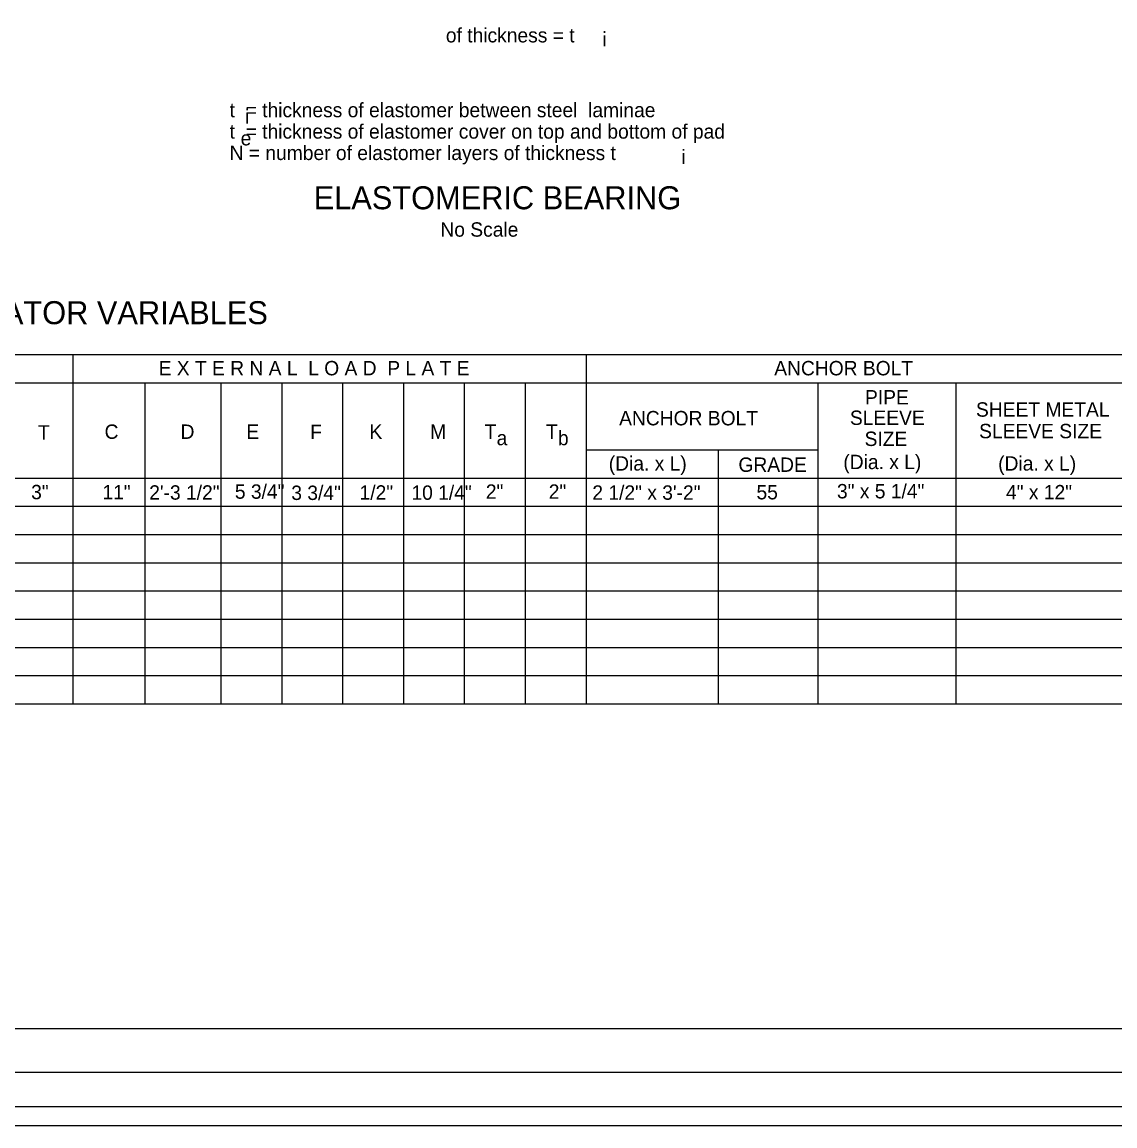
# Model space of a CAD drawing. Extents: x -194 to 226, y 505 to 725.
# Drawn here: x -47.4 to 47.6, y 505.4 to 601.4 of the extents above; entities that cross this region are included whole.
import ezdxf

# ---------------------------------------------------------------- set-up
doc = ezdxf.new("R2010")
doc.units = 0
for name, color, linetype in [('border', 7, 'Continuous'), ('Border 2660-Hwy18 - Level 62', 7, 'Continuous'), ('Border 2660-Hwy18 - Level 63', 7, 'Continuous'), ('Level 40', 7, 'Continuous'), ('Level 41', 7, 'Continuous'), ('Level 62 PDF', 7, 'Continuous'), ('Text', 7, 'Continuous')]:
    doc.layers.add(name, color=color, linetype=linetype)

msp = doc.modelspace()

# ---------------------------------------------------------------- linework, layer by layer
at = {"layer": 'border'}
msp.add_line((143.779, 513.86), (-176.332, 513.86), dxfattribs=at)
at = {"layer": 'Border 2660-Hwy18 - Level 62'}
msp.add_lwpolyline([(-192.533, 725.169), (148.651, 725.169), (148.651, 507.073), (-192.533, 507.073)], close=True, dxfattribs=at)
at = {"layer": 'Border 2660-Hwy18 - Level 63'}
msp.add_lwpolyline([(-193.644, 723.74), (146.351, 723.74), (146.351, 510.044), (-193.644, 510.044)], close=True, dxfattribs=at)
at = {"layer": 'Level 40'}
for p, q in [((-36.746, 570.011), (-36.746, 542.092)), ((-30.142, 570.011), (-30.142, 542.092)), ((-24.854, 570.011), (-24.854, 542.092)), ((-19.563, 570.011), (-19.563, 542.092)), ((-14.271, 570.011), (-14.271, 542.092)), ((-8.979, 570.011), (-8.979, 542.092)), ((-3.688, 570.011), (-3.688, 542.092)), ((0.214, 570.011), (5.33, 570.011)), ((21.757, 570.011), (21.757, 542.092)), ((33.757, 570.011), (33.757, 542.092)), ((1.604, 564.172), (21.757, 564.172)), ((13.084, 564.172), (13.084, 542.092)), ((-173.559, 561.719), (58.082, 561.719)), ((-42.997, 562.218), (-42.997, 558.728)), ((-36.746, 562.218), (-36.746, 558.728)), ((-30.142, 562.218), (-30.142, 558.728)), ((-24.854, 562.218), (-24.854, 558.728)), ((1.604, 562.218), (1.604, 558.728)), ((21.757, 562.218), (21.757, 558.728)), ((33.757, 562.218), (33.757, 558.728)), ((-173.559, 559.266), (58.082, 559.266)), ((-173.559, 556.812), (58.082, 556.812)), ((-173.559, 556.812), (58.082, 556.812)), ((-173.559, 554.359), (58.082, 554.359)), ((-173.559, 554.359), (58.082, 554.359)), ((-173.559, 551.906), (58.082, 551.906)), ((-173.559, 551.905), (58.082, 551.905)), ((-173.559, 549.452), (58.082, 549.452)), ((-173.559, 546.999), (58.082, 546.999)), ((-173.559, 544.545), (58.082, 544.545))]:
    msp.add_line(p, q, dxfattribs=at)
at = {"layer": 'Level 41'}
for p, q in [((-92.484, 572.464), (58.082, 572.464)), ((-42.997, 572.464), (-42.997, 542.092)), ((1.604, 572.464), (1.604, 542.092)), ((-173.559, 570.011), (58.082, 570.011)), ((-173.559, 542.092), (58.082, 542.092))]:
    msp.add_line(p, q, dxfattribs=at)
at = {"layer": 'Level 62 PDF'}
msp.add_lwpolyline([(-190.033, 723.503), (151.151, 723.503), (151.151, 505.407), (-190.033, 505.407)], close=True, dxfattribs=at)

# ---------------------------------------------------------------- texts
at = {"layer": 'Level 40'}
for s, p in [('of thickness = t', (-10.582, 599.588)), ('t  = thickness of elastomer between steel  laminae', (-29.384, 593.086)), ('t  = thickness of elastomer cover on top and bottom of pad', (-29.384, 591.224)), ('e', (-28.422, 590.636)), ('N = number of elastomer layers of thickness t', (-29.384, 589.363)), ('No Scale', (-11.059, 582.702)), ('E X T E R N A L  L O A D  P L A T E ', (-35.554, 570.65)), ('ANCHOR BOLT', (17.968, 570.65)), ('PIPE', (25.857, 568.117)), ('SHEET METAL', (35.506, 567.055)), ('ANCHOR BOLT', (4.482, 566.303)), ('SLEEVE', (24.546, 566.339)), ('T', (-46.037, 565.067)), ('C', (-40.252, 565.128)), ('D', (-33.644, 565.128)), ('E', (-27.931, 565.128)), ('F', (-22.376, 565.102)), ('K', (-17.224, 565.128)), ('M', (-11.952, 565.128)), ('T ', (-7.213, 565.128)), ('T ', (-1.884, 565.128)), ('SLEEVE SIZE', (35.779, 565.182)), ('a ', (-6.168, 564.577)), ('b ', (-0.839, 564.577)), ('SIZE', (25.822, 564.509)), ('(Dia. x L)', (3.581, 562.37)), ('GRADE', (14.854, 562.26)), ('(Dia. x L)', (23.974, 562.497)), ('(Dia. x L)', (37.435, 562.37)), ('3"', (-46.636, 559.882)), ('11"', (-40.439, 559.869)), ('2\'-3 1/2"', (-36.371, 559.843)), ('3 3/4"', (-24.02, 559.816)), ('1/2"', (-18.083, 559.843)), ('10 1/4"', (-13.574, 559.83)), ('2"', (-7.107, 559.921)), ('2"', (-1.637, 559.921)), ('2 1/2" x 3\'-2"', (2.154, 559.836)), ('55', (16.425, 559.869)), ('3" x 5 1/4"', (23.421, 559.954)), ('4" x 12"', (38.116, 559.869))]:
    msp.add_text(s, height=1.25, dxfattribs=at).set_placement(p)
for p in [(3.037, 599.253), (-28.047, 592.531), (9.903, 589.014)]:
    msp.add_text('i', height=1.25, rotation=360, dxfattribs=at).set_placement(p)
at = {"layer": 'Level 41'}
for s, p in [(' ELASTOMERIC BEARING ', (-22.818, 585.085)), (' TABLE OF FABRICATOR VARIABLES ', (-73.315, 575.097))]:
    msp.add_text(s, height=2, dxfattribs=at).set_placement(p)
at = {"layer": 'Text'}
msp.add_text('5 3/4"', height=1.25, dxfattribs=at).set_placement((-28.923, 559.922))

doc.saveas('drawing.dxf')
